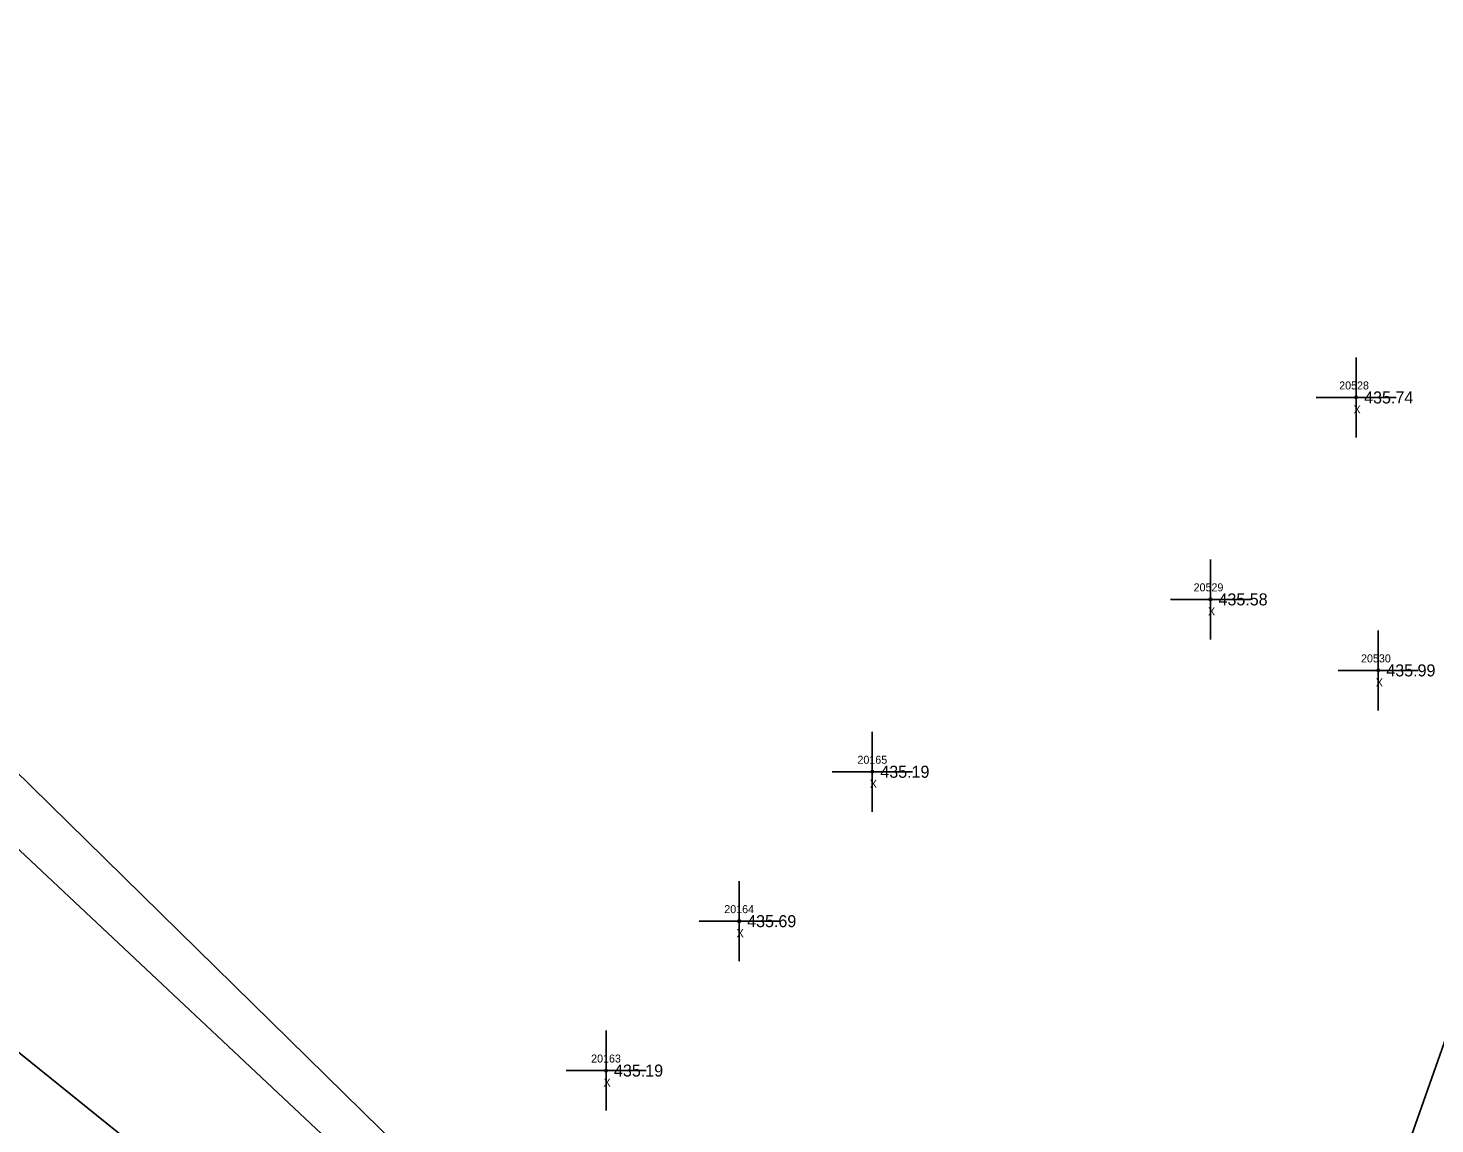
# Model space of a CAD drawing. Extents: x 1613836 to 1615109, y 777151 to 778248.
# Drawn here: x 1614329.5 to 1614505.3, y 777805.7 to 777942.5 of the extents above; entities that cross this region are included whole.
import ezdxf

# ---------------------------------------------------------------- set-up
doc = ezdxf.new("R2010")
doc.units = 0
for name, color, linetype in [('RD_DTM_BkLn2', 7, 'Continuous'), ('RD_EX_H2O', 7, 'Continuous'), ('RD_EX_Misc', 7, 'Continuous'), ('RD_EX_Misc_txCode', 7, 'Continuous'), ('RD_EX_Road', 7, 'Continuous'), ('RD_EX_TX_Misc_ELEV', 7, 'Continuous'), ('RD_SMD_Locator', 7, 'Continuous')]:
    doc.layers.add(name, color=color, linetype=linetype)

msp = doc.modelspace()

# ---------------------------------------------------------------- linework, layer by layer
at = {"layer": 'RD_DTM_BkLn2'}
for points in [[(1613870.65, 778107.91), (1613917.36, 778089.81), (1613963.47, 778068.53), (1614008.76, 778046.32), (1614052.42, 778023.01), (1614094.96, 777996.37), (1614137.71, 777969), (1614179.06, 777940.06), (1614196.49, 777927.41), (1614202.23, 777922.93), (1614210.94, 777920.91), (1614226.4, 777922.61), (1614267.62, 777889.85), (1614307.16, 777859.76), (1614381.32, 777790.21), (1614451.43, 777721.4), (1614453.49, 777722.08), (1614455.33, 777720.48), (1614437.07, 777696.16)], [(1614263.34, 777907.48), (1614273.9, 777898.51), (1614311.56, 777865.81), (1614385.12, 777793.65), (1614458.7, 777729.38), (1614464.37, 777721.53)]]:
    msp.add_lwpolyline(points, dxfattribs=at)
at = {"layer": 'RD_EX_H2O'}
msp.add_lwpolyline([(1614634.13, 778230.42), (1614629.46, 778175.6), (1614612.2, 778126.55), (1614606.67, 778108.17), (1614610.57, 778089.24), (1614615.98, 778055.09), (1614603.68, 778033.92), (1614586.84, 777977.49), (1614567.11, 777927.46), (1614559.23, 777908.74), (1614527.56, 777868.79), (1614521.38, 777849.92), (1614508, 777820.03), (1614493.75, 777779.64), (1614479.27, 777749.87), (1614469.02, 777727.63), (1614464.37, 777721.67), (1614444.52, 777689.77), (1614435.76, 777671.49)], dxfattribs=at)
at = {"layer": 'RD_EX_Misc'}
for p, q in [((1614495.49, 777891.38), (1614495.49, 777901.38)), ((1614490.49, 777896.38), (1614500.49, 777896.38)), ((1614477.29, 777866.16), (1614477.29, 777876.16)), ((1614472.29, 777871.16), (1614482.29, 777871.16)), ((1614498.26, 777857.29), (1614498.26, 777867.29)), ((1614493.26, 777862.29), (1614503.26, 777862.29)), ((1614435.03, 777844.63), (1614435.03, 777854.63)), ((1614430.03, 777849.63), (1614440.03, 777849.63)), ((1614418.39, 777825.97), (1614418.39, 777835.97)), ((1614413.39, 777830.97), (1614423.39, 777830.97)), ((1614401.75, 777807.31), (1614401.75, 777817.31)), ((1614396.75, 777812.31), (1614406.75, 777812.31))]:
    msp.add_line(p, q, dxfattribs=at)
at = {"layer": 'RD_EX_Road'}
msp.add_lwpolyline([(1613868.87, 778104.15), (1613915.02, 778083.82), (1613960.16, 778062.2), (1614004.58, 778040.28), (1614048.84, 778015.98), (1614091.38, 777990.08), (1614134.36, 777962.6), (1614174.73, 777933.48), (1614192.07, 777920.58), (1614215.93, 777904.23), (1614254.59, 777873.05), (1614293.82, 777842.42), (1614371.74, 777779.59), (1614449.33, 777716.3), (1614443.98, 777709.72), (1614439.38, 777704.09)], dxfattribs=at)
at = {"layer": 'RD_SMD_Locator'}
for centre in [(1614495.49, 777896.38), (1614477.29, 777871.16), (1614498.26, 777862.29), (1614435.03, 777849.63), (1614418.39, 777830.97), (1614401.75, 777812.31)]:
    msp.add_circle(centre, 0.15, dxfattribs=at)

# ---------------------------------------------------------------- texts
at = {"layer": 'RD_EX_Misc_txCode'}
for s, p in [('20528', (1614493.37, 777897.38)), ('X', (1614495.17, 777894.38)), ('20529', (1614475.18, 777872.16)), ('X', (1614476.98, 777869.16)), ('20530', (1614496.1, 777863.29)), ('X', (1614497.94, 777860.29)), ('20165', (1614433.17, 777850.63)), ('X', (1614434.71, 777847.63)), ('20164', (1614416.53, 777831.97)), ('X', (1614418.07, 777828.97)), ('20163', (1614399.89, 777813.31)), ('X', (1614401.44, 777810.31))]:
    msp.add_text(s, height=1, dxfattribs=at).set_placement(p)
at = {"layer": 'RD_EX_TX_Misc_ELEV'}
for s, p in [('435.74', (1614496.49, 777895.63)), ('435.58', (1614478.29, 777870.41)), ('435.99', (1614499.26, 777861.54)), ('435.19', (1614436.03, 777848.88)), ('435.69', (1614419.39, 777830.22)), ('435.19', (1614402.75, 777811.56))]:
    msp.add_text(s, height=1.5, dxfattribs=at).set_placement(p)

doc.saveas('drawing.dxf')
